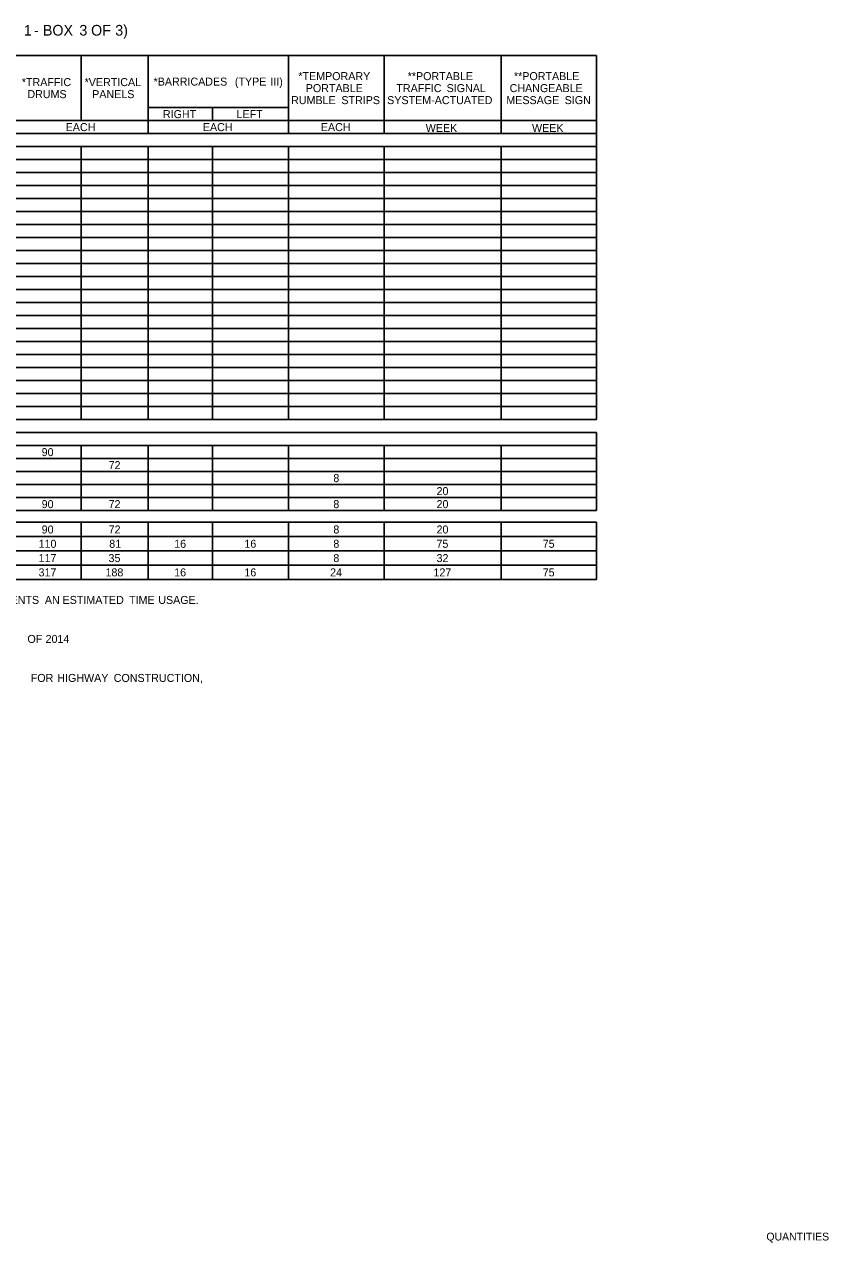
# Model space of a CAD drawing. Extents: x 542596 to 1930787, y -1948294 to 596640.
# Drawn here: x 548907 to 549510, y -1946064 to -1945150 of the extents above; entities that cross this region are included whole.
import ezdxf

# ---------------------------------------------------------------- set-up
doc = ezdxf.new("R2010")
doc.units = 0
doc.layers.add('Default', color=7, linetype='Continuous')
doc.layers.add('R_Border Prem', color=7, linetype='Continuous')

msp = doc.modelspace()

# ---------------------------------------------------------------- linework, layer by layer
at = {"layer": 'Default'}
for p, q in [((548272.08, -1945173.76), (549335.81, -1945173.76)), ((548949.22, -1945222.51), (548949.22, -1945173.76)), ((548999.43, -1945222.51), (548999.43, -1945173.76)), ((548999.43, -1945232.26), (548999.43, -1945173.76)), ((549104.73, -1945232.26), (549104.73, -1945173.76)), ((549176.4, -1945232.26), (549176.4, -1945173.76)), ((549264.15, -1945232.26), (549264.15, -1945173.76)), ((549335.81, -1945446.76), (549335.81, -1945173.76)), ((548999.43, -1945212.76), (549104.73, -1945212.76)), ((549047.7, -1945222.51), (549047.7, -1945212.76)), ((549047.7, -1945222.51), (549047.7, -1945212.76)), ((548798.58, -1945222.51), (549335.81, -1945222.51)), ((548999.43, -1945222.51), (549047.7, -1945222.51)), ((549047.7, -1945222.51), (549335.81, -1945222.51)), ((549104.73, -1945232.26), (549104.73, -1945222.51)), ((549176.4, -1945232.26), (549176.4, -1945222.51)), ((549264.15, -1945232.26), (549264.15, -1945222.51)), ((548272.08, -1945232.26), (549335.81, -1945232.26)), ((548740.57, -1945232.26), (549335.81, -1945232.26)), ((548272.08, -1945242.01), (549335.81, -1945242.01)), ((548949.22, -1945446.76), (548949.22, -1945242.01)), ((548949.22, -1945446.76), (548949.22, -1945242.01)), ((548999.43, -1945446.76), (548999.43, -1945242.01)), ((548999.43, -1945446.76), (548999.43, -1945242.01)), ((549047.7, -1945446.76), (549047.7, -1945242.01)), ((549047.7, -1945446.76), (549047.7, -1945242.01)), ((549104.73, -1945378.51), (549104.73, -1945242.01)), ((549104.73, -1945446.76), (549104.73, -1945242.01)), ((549176.4, -1945446.76), (549176.4, -1945242.01)), ((549264.15, -1945446.76), (549264.15, -1945242.01)), ((548272.08, -1945251.76), (549335.81, -1945251.76)), ((548272.08, -1945261.51), (549335.81, -1945261.51)), ((548272.08, -1945271.26), (549335.81, -1945271.26)), ((548272.08, -1945281.01), (549335.81, -1945281.01)), ((548272.08, -1945290.76), (549335.81, -1945290.76)), ((548272.08, -1945300.51), (549335.81, -1945300.51)), ((548272.08, -1945310.26), (549335.81, -1945310.26)), ((548272.08, -1945320.01), (549335.81, -1945320.01)), ((548272.08, -1945329.76), (549335.81, -1945329.76)), ((548272.08, -1945339.51), (549335.81, -1945339.51)), ((548272.08, -1945349.26), (549335.81, -1945349.26)), ((548272.08, -1945359.01), (549335.81, -1945359.01)), ((548272.08, -1945368.76), (549335.81, -1945368.76)), ((548272.08, -1945378.51), (549335.81, -1945378.51)), ((548272.08, -1945388.26), (549335.81, -1945388.26)), ((549104.73, -1945446.76), (549104.73, -1945388.26)), ((548272.08, -1945398.01), (549335.81, -1945398.01)), ((548272.08, -1945407.76), (549335.81, -1945407.76)), ((548272.08, -1945417.51), (549335.81, -1945417.51)), ((548272.08, -1945427.26), (549335.81, -1945427.26)), ((548272.08, -1945437.01), (549335.81, -1945437.01)), ((549176.4, -1945446.76), (549176.4, -1945437.01)), ((548272.08, -1945446.76), (549335.81, -1945446.76)), ((548272.08, -1945456.51), (549335.81, -1945456.51)), ((549335.81, -1945515.01), (549335.81, -1945456.51)), ((548272.08, -1945466.26), (549335.81, -1945466.26)), ((548949.22, -1945515.01), (548949.22, -1945466.26)), ((548949.22, -1945515.01), (548949.22, -1945466.26)), ((548999.43, -1945515.01), (548999.43, -1945466.26)), ((548999.43, -1945515.01), (548999.43, -1945466.26)), ((549047.7, -1945515.01), (549047.7, -1945466.26)), ((549047.7, -1945515.01), (549047.7, -1945466.26)), ((549104.73, -1945485.76), (549104.73, -1945466.26)), ((549104.73, -1945515.01), (549104.73, -1945466.26)), ((549176.4, -1945515.01), (549176.4, -1945466.26)), ((549264.15, -1945515.01), (549264.15, -1945466.26)), ((548272.08, -1945476.01), (549335.81, -1945476.01)), ((548272.08, -1945485.76), (549335.81, -1945485.76)), ((548272.08, -1945495.51), (549335.81, -1945495.51)), ((549104.73, -1945515.01), (549104.73, -1945495.51)), ((548272.08, -1945505.26), (549264.15, -1945505.26)), ((549176.4, -1945515.01), (549176.4, -1945505.26)), ((549264.15, -1945505.26), (549335.81, -1945505.26)), ((548272.08, -1945515.01), (549335.81, -1945515.01)), ((548272.08, -1945523.79), (549335.81, -1945523.79)), ((548272.08, -1945523.79), (549335.81, -1945523.79)), ((548949.22, -1945566.69), (548949.22, -1945523.79)), ((548999.43, -1945566.69), (548999.43, -1945523.79)), ((549047.7, -1945566.69), (549047.7, -1945523.79)), ((549104.73, -1945566.69), (549104.73, -1945523.79)), ((549176.4, -1945566.69), (549176.4, -1945523.79)), ((549264.15, -1945566.69), (549264.15, -1945523.79)), ((549335.81, -1945566.69), (549335.81, -1945523.79)), ((548272.08, -1945534.51), (549335.81, -1945534.51)), ((548272.08, -1945545.24), (549335.81, -1945545.24)), ((548272.08, -1945555.96), (549335.81, -1945555.96)), ((548272.08, -1945566.69), (549335.81, -1945566.69))]:
    msp.add_line(p, q, dxfattribs=at)

# ---------------------------------------------------------------- texts
for s, height, p in [(' 1', 8, (548903.37, -1945158.75)), (' -', 8, (548910.88, -1945158.75)), (' BOX', 8, (548917.62, -1945158.75)), (' 3', 8, (548944.94, -1945158.75)), (' OF', 8, (548953.77, -1945158.75)), (' 3)', 8, (548971.88, -1945158.75)), ('*TRAFFIC', 6, (548904.77, -1945196.64)), ('*VERTICAL', 6, (548951.86, -1945196.64)), ('*BARRICADES', 6, (549003.58, -1945196.26)), (' (TYPE', 6, (549062.32, -1945196.26)), (' III)', 6, (549088.93, -1945196.26)), ('*TEMPORARY', 6, (549112.14, -1945192.14)), ('**PORTABLE', 6, (549194.16, -1945192.14)), ('**PORTABLE', 6, (549273.87, -1945192.14)), ('DRUMS', 6, (548908.95, -1945205.64)), ('PANELS', 6, (548957.53, -1945205.64)), ('PORTABLE', 6, (549117.72, -1945201.14)), ('TRAFFIC', 6, (549185.68, -1945201.14)), (' SIGNAL', 6, (549221.11, -1945201.14)), ('CHANGEABLE', 6, (549270.61, -1945201.14)), ('RUMBLE', 6, (549106.74, -1945210.14)), (' STRIPS', 6, (549142.19, -1945210.14)), ('SYSTEM-ACTUATED', 6, (549178.79, -1945210.14)), ('MESSAGE', 6, (549268.14, -1945210.14)), (' SIGN', 6, (549309.66, -1945210.14)), ('RIGHT', 6, (549010.61, -1945220.64)), ('LEFT', 6, (549065.82, -1945220.64)), ('EACH', 6, (548937.66, -1945230.39)), ('EACH', 6, (549040.53, -1945230.39)), ('EACH', 6, (549129.01, -1945230.39)), ('WEEK', 6, (549207.7, -1945231.06)), ('WEEK', 6, (549287.41, -1945231.06)), ('90', 6, (548919.66, -1945474.14)), ('72', 6, (548969.89, -1945483.89)), ('8', 6, (549138.42, -1945493.64)), ('20', 6, (549215.81, -1945503.39)), ('90', 6, (548919.66, -1945513.14)), ('72', 6, (548969.88, -1945513.14)), ('8', 6, (549138.42, -1945513.14)), ('20', 6, (549215.82, -1945513.14)), ('90', 6, (548919.66, -1945532.15)), ('72', 6, (548969.88, -1945532.15)), ('8', 6, (549138.42, -1945532.15)), ('20', 6, (549215.82, -1945532.15)), ('110', 6, (548917.33, -1945542.88)), ('81', 6, (548970.35, -1945542.88)), ('16', 6, (549019.05, -1945542.88)), ('16', 6, (549071.7, -1945542.88)), ('8', 6, (549138.42, -1945542.88)), ('75', 6, (549215.74, -1945542.88)), ('75', 6, (549295.44, -1945542.88)), ('117', 6, (548917.31, -1945553.6)), ('35', 6, (548969.79, -1945553.6)), ('8', 6, (549138.42, -1945553.6)), ('32', 6, (549215.82, -1945553.6)), ('317', 6, (548917.31, -1945564.33)), ('188', 6, (548967.53, -1945564.33)), ('16', 6, (549019.05, -1945564.33)), ('16', 6, (549071.7, -1945564.33)), ('24', 6, (549136, -1945564.33)), ('127', 6, (549213.47, -1945564.33)), ('75', 6, (549295.44, -1945564.33)), (' REPRESENTS', 6, (548861.1, -1945584.99)), (' AN', 6, (548919.83, -1945584.99)), (' ESTIMATED', 6, (548933.12, -1945584.99)), (' TIME', 6, (548982.98, -1945584.99)), (' USAGE.', 6, (549004.89, -1945584.99)), (' OF', 6, (548906.77, -1945614.24)), (' 2014', 6, (548920.36, -1945614.24)), (' FOR', 6, (548909.25, -1945643.49)), (' HIGHWAY', 6, (548929.16, -1945643.49)), (' CONSTRUCTION,', 6, (548971.48, -1945643.49))]:
    msp.add_text(s, height=height, dxfattribs=at).set_placement(p)
at = {"layer": 'R_Border Prem'}
msp.add_text('QUANTITIES', height=5.862, rotation=360, dxfattribs=at).set_placement((549463.18, -1946062.39))

doc.saveas('drawing.dxf')
